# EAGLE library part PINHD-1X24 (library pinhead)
PIN HEADER
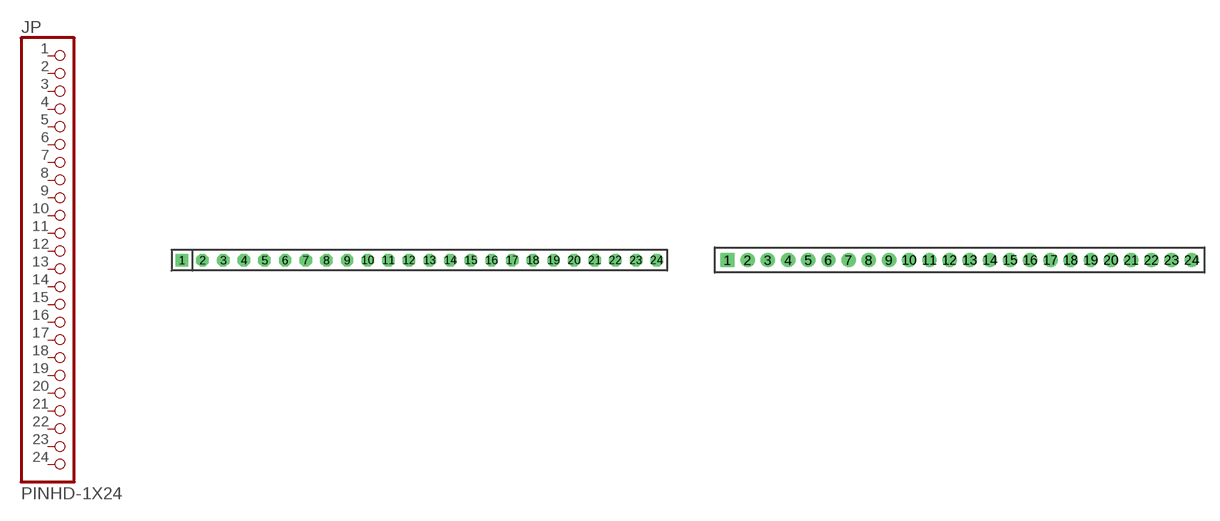
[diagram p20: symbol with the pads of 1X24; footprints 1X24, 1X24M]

Designator prefix JP

## PINHD-1X24  [1X24]
1  1  pas
2  2  pas
3  3  pas
4  4  pas
5  5  pas
6  6  pas
7  7  pas
8  8  pas
9  9  pas
10  10  pas
11  11  pas
12  12  pas
13  13  pas
14  14  pas
15  15  pas
16  16  pas
17  17  pas
18  18  pas
19  19  pas
20  20  pas
21  21  pas
22  22  pas
23  23  pas
24  24  pas

## PINHD-1X24M  [1X24M]
Pads as for 1X24

## Footprint 1X24 (pad centres in mm)
PIN HEADER - 0.1"
drill 1.016 square: 1 -29.21,0
drill 1.016 octagon: 2 -26.67,0; 3 -24.13,0; 4 -21.59,0; 5 -19.05,0; 6 -16.51,0; 7 -13.97,0; 8 -11.43,0; 9 -8.89,0; 10 -6.35,0; 11 -3.81,0; 12 -1.27,0; 13 1.27,0; 14 3.81,0; 15 6.35,0; 16 8.89,0; 17 11.43,0; 18 13.97,0; 19 16.51,0; 20 19.05,0; 21 21.59,0; 22 24.13,0; 23 26.67,0; 24 29.21,0

## Footprint 1X24M (pad centres in mm)
PIN HEADER - 2MM"
drill 0.914 square: 1 -23,0
drill 0.914 round: 2 -21,0; 3 -19,0; 4 -17,0; 5 -15,0; 6 -13,0; 7 -11,0; 8 -9,0; 9 -7,0; 10 -5,0; 11 -3,0; 12 -1,0; 13 1,0; 14 3,0; 15 5,0; 16 7,0; 17 9,0; 18 11,0; 19 13,0; 20 15,0; 21 17,0; 22 19,0; 23 21,0; 24 23,0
